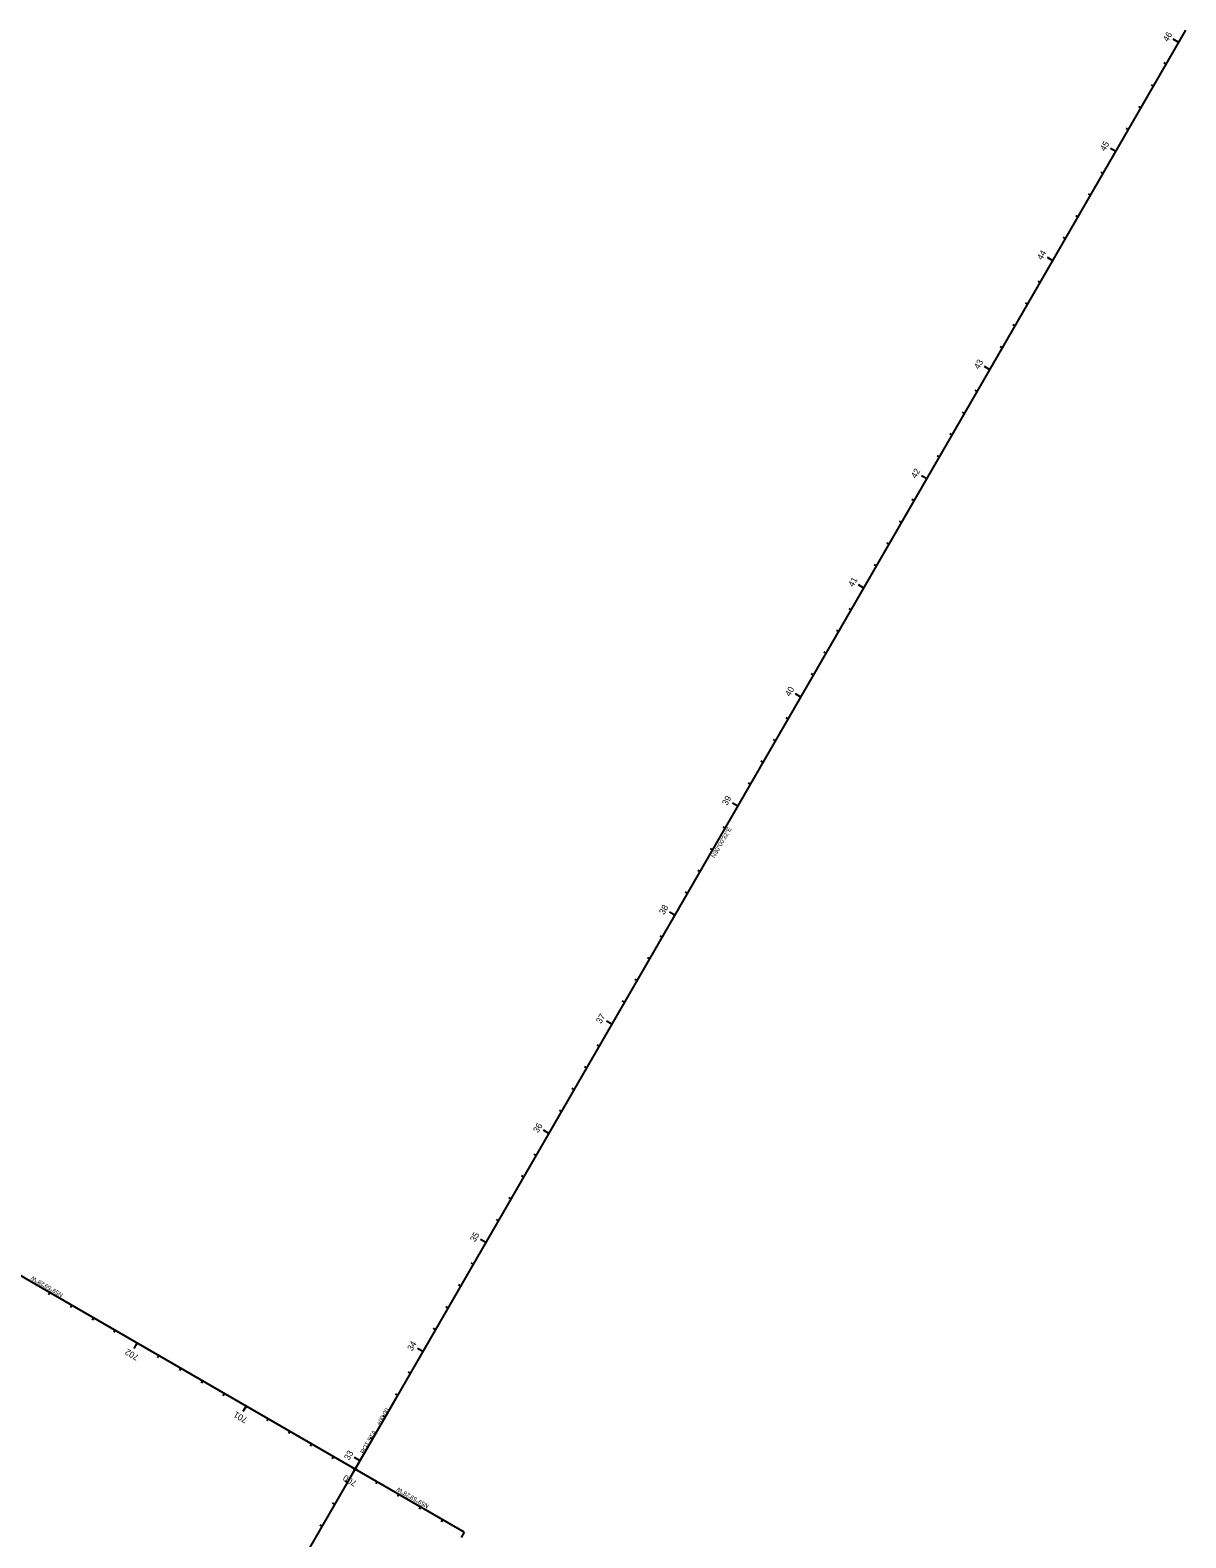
# Model space of a CAD drawing. Extents: x 2005660 to 2007493, y 401364 to 404817.
# Drawn here: x 2006576 to 2007493, y 402588 to 403785 of the extents above; entities that cross this region are included whole.
import ezdxf

# ---------------------------------------------------------------- set-up
doc = ezdxf.new("R2010")
doc.units = 0
for name, color, linetype in [('ConstLines', 7, 'Continuous'), ('CurbBack', 7, 'Continuous'), ('CurbFace', 7, 'Continuous'), ('PavtAsphalt', 7, 'Continuous'), ('PavtAsphalt_ep', 7, 'Continuous'), ('PavtMilling', 7, 'Continuous'), ('ScratchEle_dp', 7, 'Continuous'), ('ShldrPaved', 7, 'Continuous'), ('SidewalkFront', 7, 'Continuous'), ('TextAlgnTicks5000', 7, 'Continuous'), ('TrafSeparator', 7, 'Continuous')]:
    doc.layers.add(name, color=color, linetype=linetype)

msp = doc.modelspace()

# ---------------------------------------------------------------- linework, layer by layer
at = {"layer": 'PavtAsphalt'}
for p, q in [((2007487.6, 403775.3), (2007483.3, 403777.8)), ((2007477.6, 403758), (2007475.9, 403759)), ((2007467.6, 403740.7), (2007465.9, 403741.7)), ((2007457.6, 403723.4), (2007455.9, 403724.4)), ((2007447.6, 403706), (2007445.9, 403707)), ((2007437.6, 403688.7), (2007433.3, 403691.2)), ((2007427.6, 403671.4), (2007425.9, 403672.4)), ((2007417.6, 403654.1), (2007415.9, 403655.1)), ((2007407.6, 403636.8), (2007405.9, 403637.8)), ((2007397.6, 403619.4), (2007395.9, 403620.4)), ((2007387.6, 403602.1), (2007383.3, 403604.6)), ((2007377.6, 403584.8), (2007375.9, 403585.8)), ((2007367.6, 403567.5), (2007365.9, 403568.5)), ((2007357.6, 403550.2), (2007355.9, 403551.2)), ((2007347.6, 403532.8), (2007345.9, 403533.8)), ((2007337.6, 403515.5), (2007333.3, 403518)), ((2007327.6, 403498.2), (2007325.9, 403499.2)), ((2007317.6, 403480.9), (2007315.9, 403481.9)), ((2007307.6, 403463.6), (2007305.9, 403464.6)), ((2007297.6, 403446.2), (2007295.9, 403447.2)), ((2007287.6, 403428.9), (2007283.3, 403431.4)), ((2007277.6, 403411.6), (2007275.8, 403412.6)), ((2007267.6, 403394.3), (2007265.8, 403395.3)), ((2007257.6, 403377), (2007255.8, 403378)), ((2007247.6, 403359.7), (2007245.8, 403360.7)), ((2007237.6, 403342.3), (2007233.2, 403344.8)), ((2007227.6, 403325), (2007225.8, 403326)), ((2007217.6, 403307.7), (2007215.8, 403308.7)), ((2007207.6, 403290.4), (2007205.8, 403291.4)), ((2007197.6, 403273.1), (2007195.8, 403274.1)), ((2007187.6, 403255.7), (2007183.2, 403258.2)), ((2007177.6, 403238.4), (2007175.8, 403239.4)), ((2007167.5, 403221.1), (2007165.8, 403222.1)), ((2007157.5, 403203.8), (2007155.8, 403204.8)), ((2007147.5, 403186.5), (2007145.8, 403187.5)), ((2007137.5, 403169.1), (2007133.2, 403171.6)), ((2007127.5, 403151.8), (2007125.8, 403152.8)), ((2007117.5, 403134.5), (2007115.8, 403135.5)), ((2007107.5, 403117.2), (2007105.8, 403118.2)), ((2007097.5, 403099.9), (2007095.8, 403100.9)), ((2007087.5, 403082.6), (2007083.2, 403085.1)), ((2007077.5, 403065.2), (2007075.8, 403066.2)), ((2007067.5, 403047.9), (2007065.8, 403048.9)), ((2007057.5, 403030.6), (2007055.8, 403031.6)), ((2007047.5, 403013.3), (2007045.8, 403014.3)), ((2007037.5, 402996), (2007033.2, 402998.5)), ((2007027.5, 402978.6), (2007025.8, 402979.6)), ((2007017.5, 402961.3), (2007015.8, 402962.3)), ((2007007.5, 402944), (2007005.8, 402945)), ((2006997.5, 402926.7), (2006995.8, 402927.7)), ((2006987.5, 402909.4), (2006983.2, 402911.9)), ((2006977.5, 402892), (2006975.8, 402893)), ((2006967.5, 402874.7), (2006965.8, 402875.7)), ((2006957.5, 402857.4), (2006955.8, 402858.4)), ((2006947.5, 402840.1), (2006945.8, 402841.1)), ((2006937.5, 402822.8), (2006933.2, 402825.3)), ((2006927.5, 402805.4), (2006925.8, 402806.4)), ((2006591.2, 402783), (2006590.2, 402781.3)), ((2006917.5, 402788.1), (2006915.8, 402789.1)), ((2006608.5, 402773), (2006607.5, 402771.3)), ((2006907.5, 402770.8), (2006905.7, 402771.8)), ((2006625.8, 402763), (2006624.8, 402761.3)), ((2006643.1, 402753), (2006642.1, 402751.3)), ((2006897.5, 402753.5), (2006895.7, 402754.5)), ((2006660.4, 402743), (2006657.9, 402738.7)), ((2006677.8, 402733), (2006676.8, 402731.2)), ((2006887.5, 402736.2), (2006883.1, 402738.7)), ((2006695.1, 402723), (2006694.1, 402721.2)), ((2006877.5, 402718.9), (2006875.7, 402719.9)), ((2006712.4, 402713), (2006711.4, 402711.2)), ((2006729.7, 402703), (2006728.7, 402701.2)), ((2006867.5, 402701.5), (2006865.7, 402702.5)), ((2006747, 402693), (2006744.5, 402688.6)), ((2006857.5, 402684.2), (2006855.7, 402685.2)), ((2006764.4, 402683), (2006763.4, 402681.2)), ((2006781.7, 402673), (2006780.7, 402671.2)), ((2006799, 402663), (2006798, 402661.2)), ((2006847.5, 402666.9), (2006845.7, 402667.9)), ((2006816.3, 402653), (2006815.3, 402651.2)), ((2006837.5, 402649.6), (2006833.1, 402652.1)), ((2006833.6, 402643), (2006831.1, 402638.6)), ((2006827.5, 402632.3), (2006825.7, 402633.3)), ((2006851, 402633), (2006850, 402631.2)), ((2006817.5, 402614.9), (2006815.7, 402615.9)), ((2006868.3, 402622.9), (2006867.3, 402621.2)), ((2006885.6, 402612.9), (2006884.6, 402611.2)), ((2006902.9, 402602.9), (2006901.9, 402601.2)), ((2006807.5, 402597.6), (2006805.7, 402598.6)), ((2006920.2, 402592.9), (2006917.7, 402588.6))]:
    msp.add_line(p, q, dxfattribs=at)
at = {"layer": 'PavtAsphalt_ep'}
for p, q in [((2006751.4, 402500.6), (2007493.3, 403785.1)), ((2006833.6, 402643), (2006339.4, 402928.4)), ((2006920.2, 402592.9), (2006833.6, 402643))]:
    msp.add_line(p, q, dxfattribs=at)
at = {"layer": 'ScratchEle_dp'}
for p, q in [((2007487.6, 403775.3), (2007485.9, 403776.3)), ((2007437.6, 403688.7), (2007433.3, 403691.2)), ((2007387.6, 403602.1), (2007385.9, 403603.1)), ((2007337.6, 403515.5), (2007335.9, 403516.5)), ((2007287.6, 403428.9), (2007285.8, 403429.9)), ((2007237.6, 403342.3), (2007235.8, 403343.3)), ((2007187.6, 403255.7), (2007183.2, 403258.2)), ((2007137.5, 403169.1), (2007135.8, 403170.1)), ((2007087.5, 403082.6), (2007085.8, 403083.6)), ((2007037.5, 402996), (2007035.8, 402997)), ((2006987.5, 402909.4), (2006985.8, 402910.4)), ((2006937.5, 402822.8), (2006933.2, 402825.3)), ((2006660.4, 402743), (2006659.4, 402741.2)), ((2006887.5, 402736.2), (2006885.7, 402737.2)), ((2006747, 402693), (2006746, 402691.2)), ((2006837.5, 402649.6), (2006835.7, 402650.6)), ((2006833.6, 402643), (2006831.1, 402638.6)), ((2006920.2, 402592.9), (2006919.2, 402591.2))]:
    msp.add_line(p, q, dxfattribs=at)
at = {"layer": 'SidewalkFront'}
msp.add_line((2006833.6, 402643), (2006866.1, 402699.2), dxfattribs=at)
msp.add_circle((2006833.6, 402643), 1, dxfattribs=at)
at = {"layer": 'TextAlgnTicks5000'}
for p, q in [((2007187.6, 403255.7), (2007185.8, 403256.7)), ((2006833.6, 402643), (2006831.1, 402638.6))]:
    msp.add_line(p, q, dxfattribs=at)
at = {"layer": 'TrafSeparator'}
for p, q in [((2007487.6, 403775.3), (2007485.9, 403776.3)), ((2007387.6, 403602.1), (2007385.9, 403603.1)), ((2007287.6, 403428.9), (2007285.8, 403429.9)), ((2007187.6, 403255.7), (2007183.2, 403258.2)), ((2007087.5, 403082.6), (2007085.8, 403083.6)), ((2006987.5, 402909.4), (2006985.8, 402910.4)), ((2006660.4, 402743), (2006659.4, 402741.2)), ((2006887.5, 402736.2), (2006885.7, 402737.2)), ((2006833.6, 402643), (2006831.1, 402638.6))]:
    msp.add_line(p, q, dxfattribs=at)

# ---------------------------------------------------------------- texts
at = {"layer": 'ConstLines'}
for s, rotation, p in [('45', 59.9911, (2007429, 403688.7)), ('40', 59.9911, (2007178.9, 403255.8)), ('35', 59.9911, (2006928.8, 402822.8)), ('700', 149.9911, (2006835.5, 402633.2))]:
    msp.add_text(s, height=4.98, rotation=rotation, dxfattribs=at).set_placement(p)
at = {"layer": 'CurbBack'}
for s, rotation, p in [('40', 59.9911, (2007178.9, 403255.8)), ('700', 149.9911, (2006835.5, 402633.2))]:
    msp.add_text(s, height=4.98, rotation=rotation, dxfattribs=at).set_placement(p)
at = {"layer": 'CurbFace'}
msp.add_text('700', height=4.98, rotation=149.9911, dxfattribs=at).set_placement((2006835.5, 402633.2))
at = {"layer": 'PavtMilling'}
for s, rotation, p in [('46', 59.9911, (2007479, 403775.4)), ('45', 59.9911, (2007429, 403688.7)), ('44', 59.9911, (2007379, 403602.2)), ('43', 59.9911, (2007328.9, 403515.5)), ('42', 59.9911, (2007278.9, 403428.9)), ('41', 59.9911, (2007229.1, 403342.7)), ('40', 59.9911, (2007178.9, 403255.8)), ('39', 59.9911, (2007128.9, 403169.2)), ('38', 59.9911, (2007078.9, 403082.6)), ('37', 59.9911, (2007028.9, 402996.1)), ('36', 59.9911, (2006978.9, 402909.4)), ('35', 59.9911, (2006928.8, 402822.8)), ('34', 59.9911, (2006878.9, 402736.3)), ('702', 149.9911, (2006662.4, 402733.2)), ('701', 149.9911, (2006748.6, 402683.4)), ('33', 59.9911, (2006828.8, 402649.6)), ('700', 149.9911, (2006835.5, 402633.2))]:
    msp.add_text(s, height=4.98, rotation=rotation, dxfattribs=at).set_placement(p)
at = {"layer": 'ShldrPaved'}
for s, rotation, p in [('N30°00\'32"E', 59.9911, (2007119.1, 403127.6)), ('N59°59\'28"W', 149.9911, (2006602.1, 402782.2)), ('N59°59\'28"W', 149.9911, (2006892.5, 402614.5))]:
    msp.add_text(s, height=3.48, rotation=rotation, dxfattribs=at).set_placement(p)
at = {"layer": 'SidewalkFront'}
for s, p in [('+00.00', (2006853.4, 402677.2)), (' STA. ', (2006845.3, 402663.2)), ('POT', (2006840.5, 402654.8))]:
    msp.add_text(s, height=3.48, rotation=59.9911, dxfattribs=at).set_placement(p)

doc.saveas('drawing.dxf')
